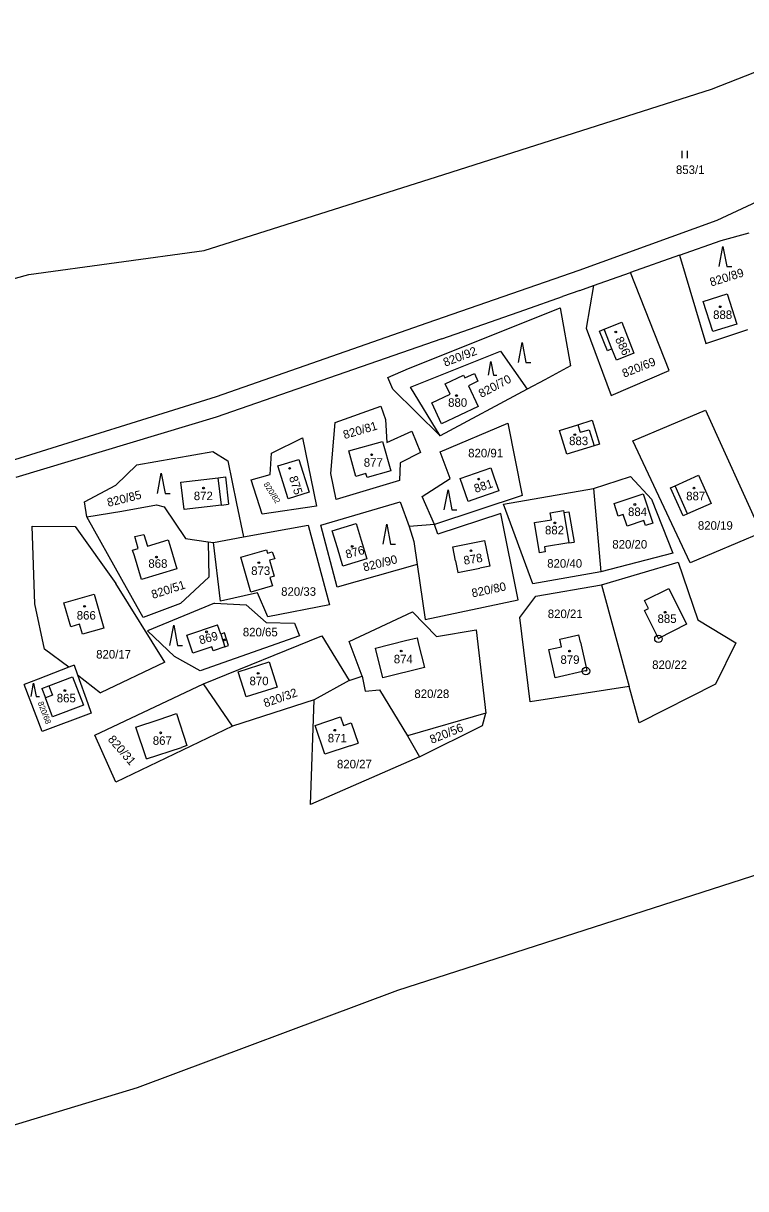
# Model space of a CAD drawing. Extents: x -779596 to -776743, y -1030330 to -1024513.
# Drawn here: x -778278.9 to -778135, y -1026649.8 to -1026417.6 of the extents above; entities that cross this region are included whole.
import ezdxf

# ---------------------------------------------------------------- set-up
doc = ezdxf.new("R2010")
doc.units = 0
for name, color, linetype in [('hranice parcel', 7, 'Continuous'), ('hranice vnitřní', 7, 'Continuous'), ('K_Ú_ hranice', 7, 'Continuous'), ('kultura', 7, 'Continuous'), ('Kód', 7, 'Continuous'), ('č_pacel stav_', 7, 'Continuous'), ('č_parcel poz_', 7, 'Continuous')]:
    doc.layers.add(name, color=color, linetype=linetype)

msp = doc.modelspace()

# ---------------------------------------------------------------- linework, layer by layer
at = {"layer": 'hranice parcel'}
for points in [[(-778140.67, -1026456.85), (-778120.81, -1026447.58)], [(-778168.21, -1026466.82), (-778140.67, -1026456.85)], [(-778139.89, -1026460.93), (-778134.32, -1026459.36)], [(-778148.19, -1026463.85), (-778139.89, -1026460.93)], [(-778148.19, -1026463.85), (-778157.94, -1026467.29)], [(-778148.19, -1026463.85), (-778142.95, -1026481.44)], [(-778198.44, -1026477.3), (-778168.21, -1026466.82)], [(-778165.32, -1026469.89), (-778157.94, -1026467.29)], [(-778150.27, -1026486.79), (-778157.94, -1026467.29)], [(-778168.08, -1026470.86), (-778171.48, -1026472.05)], [(-778168.08, -1026470.86), (-778165.32, -1026469.89)], [(-778165.32, -1026469.89), (-778166.78, -1026478.37)], [(-778143.46, -1026473.02), (-778138.7, -1026471.52)], [(-778138.7, -1026471.52), (-778136.8, -1026477.57)], [(-778179.03, -1026474.69), (-778171.48, -1026472.05)], [(-778141.57, -1026479.06), (-778143.46, -1026473.02)], [(-778195.58, -1026480.48), (-778179.03, -1026474.69)], [(-778178.4, -1026476.9), (-778172.01, -1026474.34)], [(-778172.01, -1026474.34), (-778169.92, -1026485.88)], [(-778240.45, -1026491.98), (-778198.44, -1026477.3)], [(-778202.16, -1026486.42), (-778178.4, -1026476.9)], [(-778166.78, -1026478.37), (-778161.82, -1026491.78)], [(-778163.21, -1026478.56), (-778159.7, -1026477.18)], [(-778159.7, -1026477.18), (-778157.28, -1026483.36)], [(-778136.8, -1026477.57), (-778141.57, -1026479.06)], [(-778195.58, -1026480.48), (-778240.48, -1026496.1)], [(-778164.14, -1026478.93), (-778163.21, -1026478.56)], [(-778162.58, -1026482.88), (-778164.14, -1026478.93)], [(-778142.95, -1026481.44), (-778134.57, -1026478.6)], [(-778201.77, -1026490.12), (-778183.84, -1026482.92)], [(-778183.84, -1026482.92), (-778178.58, -1026490.54)], [(-778161.67, -1026482.48), (-778162.58, -1026482.88)], [(-778160.78, -1026484.74), (-778161.67, -1026482.48)], [(-778157.28, -1026483.36), (-778160.78, -1026484.74)], [(-778206.29, -1026488.21), (-778202.16, -1026486.42)], [(-778194.9, -1026489.43), (-778191.25, -1026487.72)], [(-778191.25, -1026487.72), (-778190.98, -1026488.29)], [(-778190.98, -1026488.29), (-778189.06, -1026487.39)], [(-778189.06, -1026487.39), (-778188.36, -1026488.95)], [(-778169.92, -1026485.88), (-778175.06, -1026488.65)], [(-778161.82, -1026491.78), (-778150.27, -1026486.79)], [(-778205.29, -1026490.51), (-778206.29, -1026488.21)], [(-778195.86, -1026499.83), (-778201.77, -1026490.12)], [(-778193.92, -1026491.51), (-778194.9, -1026489.43)], [(-778188.36, -1026488.95), (-778190.25, -1026489.84)], [(-778190.25, -1026489.84), (-778188.3, -1026494)], [(-778175.06, -1026488.65), (-778178.58, -1026490.54)], [(-778281.69, -1026504.86), (-778240.45, -1026491.98)], [(-778205.29, -1026490.51), (-778195.86, -1026499.83)], [(-778197.56, -1026493.22), (-778193.92, -1026491.51)], [(-778178.58, -1026490.54), (-778195.86, -1026499.83)], [(-778216.78, -1026497.13), (-778207.69, -1026493.91)], [(-778207.69, -1026493.91), (-778206.8, -1026496.54)], [(-778195.59, -1026497.42), (-778197.56, -1026493.22)], [(-778188.3, -1026494), (-778195.59, -1026497.42)], [(-778157.51, -1026500.8), (-778143.02, -1026494.69)], [(-778143.02, -1026494.69), (-778131.92, -1026519.13)], [(-778240.48, -1026496.1), (-778280.39, -1026508.11)], [(-778206.8, -1026496.54), (-778206.52, -1026501.12)], [(-778168.48, -1026497.61), (-778165.61, -1026496.71)], [(-778165.61, -1026496.71), (-778164.16, -1026501.46)], [(-778217.66, -1026507.33), (-778216.78, -1026497.13)], [(-778206.52, -1026501.12), (-778201.52, -1026498.91)], [(-778201.52, -1026498.91), (-778199.83, -1026503.11)], [(-778195.9, -1026503), (-778182.42, -1026497.27)], [(-778182.42, -1026497.27), (-778179.57, -1026511.72)], [(-778172.11, -1026498.74), (-778168.48, -1026497.61)], [(-778170.63, -1026503.48), (-778172.11, -1026498.74)], [(-778229.5, -1026503.25), (-778223.31, -1026500.24)], [(-778223.31, -1026500.24), (-778220.55, -1026513.82)], [(-778214.1, -1026502.83), (-778207.35, -1026500.96)], [(-778207.35, -1026500.96), (-778205.72, -1026506.82)], [(-778164.16, -1026501.46), (-778165.2, -1026501.78)], [(-778146.07, -1026525.15), (-778157.51, -1026500.8)], [(-778256.29, -1026505.58), (-778241.15, -1026502.97)], [(-778241.15, -1026502.97), (-778238.2, -1026504.77)], [(-778229.78, -1026507.52), (-778229.5, -1026503.25)], [(-778212.7, -1026507.89), (-778214.1, -1026502.83)], [(-778199.83, -1026503.11), (-778203.82, -1026505.19)], [(-778193.87, -1026508.32), (-778195.9, -1026503)], [(-778165.2, -1026501.78), (-778170.63, -1026503.48)], [(-778260.5, -1026509.62), (-778256.29, -1026505.58)], [(-778238.2, -1026504.77), (-778236.43, -1026513.27)], [(-778228.21, -1026505.82), (-778224.05, -1026504.52)], [(-778226.15, -1026512.36), (-778228.21, -1026505.82)], [(-778224.05, -1026504.52), (-778222, -1026511.05)], [(-778203.82, -1026505.19), (-778204, -1026508.72)], [(-778191.89, -1026508.3), (-778185.79, -1026506.2)], [(-778185.79, -1026506.2), (-778185.1, -1026508.2)], [(-778247.51, -1026509.03), (-778240.1, -1026508.17)], [(-778240.1, -1026508.17), (-778238.66, -1026508)], [(-778238.66, -1026508), (-778238.02, -1026513.46)], [(-778233.54, -1026508.56), (-778229.78, -1026507.52)], [(-778231.37, -1026515.42), (-778233.54, -1026508.56)], [(-778216.62, -1026512.53), (-778217.66, -1026507.33)], [(-778204, -1026508.72), (-778216.62, -1026512.53)], [(-778210.66, -1026507.32), (-778212.7, -1026507.89)], [(-778210.44, -1026508.12), (-778210.66, -1026507.32)], [(-778205.72, -1026506.82), (-778210.44, -1026508.12)], [(-778199.47, -1026511.89), (-778193.87, -1026508.32)], [(-778190.3, -1026512.9), (-778191.89, -1026508.3)], [(-778185.1, -1026508.2), (-778184.2, -1026510.8)], [(-778165.31, -1026510.3), (-778157.98, -1026507.9)], [(-778157.98, -1026507.9), (-778153.78, -1026512.43)], [(-778149.09, -1026509.76), (-778144.4, -1026507.67)], [(-778144.4, -1026507.67), (-778141.9, -1026513.28)], [(-778266.71, -1026512.96), (-778260.5, -1026509.62)], [(-778246.87, -1026514.5), (-778247.51, -1026509.03)], [(-778184.2, -1026510.8), (-778188.22, -1026512.19)], [(-778183.28, -1026513.41), (-778165.31, -1026510.3)], [(-778165.31, -1026510.3), (-778163.89, -1026526.93)], [(-778149.97, -1026510.15), (-778149.09, -1026509.76)], [(-778147.46, -1026515.77), (-778149.97, -1026510.15)], [(-778266.28, -1026515.95), (-778266.71, -1026512.96)], [(-778236.43, -1026513.27), (-778235.04, -1026519.97)], [(-778222, -1026511.05), (-778226.15, -1026512.36)], [(-778219.63, -1026517.6), (-778203.86, -1026512.95)], [(-778203.86, -1026512.95), (-778202.03, -1026517.87)], [(-778197, -1026517.48), (-778199.47, -1026511.89)], [(-778179.57, -1026511.72), (-778197, -1026517.48)], [(-778188.22, -1026512.19), (-778190.3, -1026512.9)], [(-778161.25, -1026513.33), (-778155.47, -1026511.37)], [(-778160.39, -1026515.85), (-778161.25, -1026513.33)], [(-778155.47, -1026511.37), (-778153.5, -1026517.2)], [(-778153.78, -1026512.43), (-778149.56, -1026523.17)], [(-778141.9, -1026513.28), (-778146.6, -1026515.38)], [(-778266.28, -1026515.95), (-778259.28, -1026514.85)], [(-778259.28, -1026514.85), (-778252.39, -1026513.58)], [(-778252.39, -1026513.58), (-778250.89, -1026513.99)], [(-778250.89, -1026513.99), (-778246.59, -1026520.27)], [(-778239.42, -1026513.62), (-778246.87, -1026514.5)], [(-778239.42, -1026513.62), (-778238.02, -1026513.46)], [(-778220.55, -1026513.82), (-778231.37, -1026515.42)], [(-778183.77, -1026515.3), (-778196.32, -1026519.38)], [(-778180.34, -1026532.5), (-778183.77, -1026515.3)], [(-778177.43, -1026529.32), (-778183.28, -1026513.41)], [(-778173.95, -1026515.16), (-778171.29, -1026514.72)], [(-778173.72, -1026516.52), (-778173.95, -1026515.16)], [(-778171.29, -1026514.72), (-778171.22, -1026515.12)], [(-778171.22, -1026515.12), (-778170.23, -1026514.95)], [(-778170.23, -1026514.95), (-778169.19, -1026520.97)], [(-778159.42, -1026515.52), (-778160.39, -1026515.85)], [(-778158.64, -1026517.84), (-778159.42, -1026515.52)], [(-778146.6, -1026515.38), (-778147.46, -1026515.77)], [(-778276.65, -1026533.32), (-778277.13, -1026517.79)], [(-778277.13, -1026517.79), (-778268.59, -1026517.9)], [(-778268.59, -1026517.9), (-778260.5, -1026529.26)], [(-778259.31, -1026528.41), (-778266.28, -1026515.95)], [(-778235.04, -1026519.97), (-778222.17, -1026517.63)], [(-778222.17, -1026517.63), (-778217.9, -1026533.51)], [(-778216.39, -1026529.98), (-778219.63, -1026517.6)], [(-778217.4, -1026518.77), (-778212.63, -1026517.3)], [(-778212.63, -1026517.3), (-778211.61, -1026520.63)], [(-778197, -1026517.48), (-778202.03, -1026517.87)], [(-778202.03, -1026517.87), (-778201.1, -1026520.9)], [(-778196.32, -1026519.38), (-778197, -1026517.48)], [(-778177.07, -1026517.07), (-778173.72, -1026516.52)], [(-778176.07, -1026523.12), (-778177.07, -1026517.07)], [(-778155.31, -1026516.71), (-778158.64, -1026517.84)], [(-778154.98, -1026517.69), (-778155.31, -1026516.71)], [(-778153.5, -1026517.2), (-778154.98, -1026517.69)], [(-778256.73, -1026519.88), (-778254.88, -1026519.45)], [(-778256.01, -1026522.26), (-778256.73, -1026519.88)], [(-778254.88, -1026519.45), (-778254.18, -1026521.79)], [(-778246.59, -1026520.27), (-778242.1, -1026520.92)], [(-778241.03, -1026521.06), (-778235.04, -1026519.97)], [(-778216.36, -1026522.15), (-778217.4, -1026518.77)], [(-778131.92, -1026519.13), (-778146.07, -1026525.15)], [(-778257.14, -1026522.6), (-778256.01, -1026522.26)], [(-778256.8, -1026523.72), (-778257.14, -1026522.6)], [(-778254.18, -1026521.79), (-778250.08, -1026520.55)], [(-778250.08, -1026520.55), (-778249.76, -1026521.6)], [(-778249.76, -1026521.6), (-778248.33, -1026526.33)], [(-778242.1, -1026520.92), (-778241.95, -1026527.99)], [(-778242.1, -1026520.92), (-778241.03, -1026521.06)], [(-778239.67, -1026532.74), (-778241.03, -1026521.06)], [(-778235.61, -1026523.97), (-778230.49, -1026522.5)], [(-778230.49, -1026522.5), (-778230.29, -1026523.22)], [(-778215.24, -1026525.79), (-778216.36, -1026522.15)], [(-778211.61, -1026520.63), (-778210.47, -1026524.33)], [(-778201.1, -1026520.9), (-778200.44, -1026525.48)], [(-778193.38, -1026521.93), (-778187.04, -1026520.66)], [(-778192.82, -1026524.71), (-778193.38, -1026521.93)], [(-778187.04, -1026520.66), (-778186.01, -1026525.78)], [(-778170.23, -1026521.14), (-778175.11, -1026521.95)], [(-778175.11, -1026521.95), (-778174.95, -1026522.94)], [(-778170.23, -1026521.14), (-778169.19, -1026520.97)], [(-778255.37, -1026528.46), (-778256.8, -1026523.72)], [(-778233.6, -1026530.94), (-778235.61, -1026523.97)], [(-778230.29, -1026523.22), (-778229.32, -1026522.94)], [(-778228.84, -1026524.31), (-778229.89, -1026524.61)], [(-778229.89, -1026524.61), (-778228.97, -1026527.8)], [(-778229.32, -1026522.94), (-778228.84, -1026524.31)], [(-778210.47, -1026524.33), (-778215.24, -1026525.79)], [(-778192.82, -1026524.71), (-778192.35, -1026527.05)], [(-778174.95, -1026522.94), (-778176.07, -1026523.12)], [(-778149.56, -1026523.17), (-778163.89, -1026526.93)], [(-778248.33, -1026526.33), (-778255.37, -1026528.46)], [(-778200.44, -1026525.48), (-778216.39, -1026529.98)], [(-778200.44, -1026525.48), (-778198.88, -1026536.38)], [(-778192.35, -1026527.05), (-778187.95, -1026526.17)], [(-778186.01, -1026525.78), (-778187.95, -1026526.17)], [(-778163.89, -1026526.93), (-778177.43, -1026529.32)], [(-778163.76, -1026529.48), (-778148.47, -1026525.01)], [(-778148.47, -1026525.01), (-778144.58, -1026536.46)], [(-778250.7, -1026544.92), (-778260.5, -1026529.26)], [(-778255.05, -1026536.01), (-778259.31, -1026528.41)], [(-778241.95, -1026527.99), (-778247.59, -1026533.25)], [(-778228.97, -1026527.8), (-778229.79, -1026528.04)], [(-778229.79, -1026528.04), (-778229.31, -1026529.7)], [(-778176.82, -1026531.74), (-778163.76, -1026529.48)], [(-778163.76, -1026529.48), (-778158.24, -1026549.77)], [(-778270.83, -1026533.06), (-778264.8, -1026531.37)], [(-778264.8, -1026531.37), (-778262.9, -1026538.13)], [(-778232.29, -1026531.12), (-778239.67, -1026532.74)], [(-778229.31, -1026529.7), (-778233.6, -1026530.94)], [(-778230.19, -1026535.88), (-778232.29, -1026531.12)], [(-778179.98, -1026536.04), (-778176.82, -1026531.74)], [(-778155.17, -1026532.64), (-778150.34, -1026530.23)], [(-778150.34, -1026530.23), (-778146.78, -1026537.36)], [(-778274.7, -1026542.33), (-778276.65, -1026533.32)], [(-778269.48, -1026537.86), (-778270.83, -1026533.06)], [(-778247.59, -1026533.25), (-778255.05, -1026536.01)], [(-778240.82, -1026533.18), (-778254.2, -1026538.67)], [(-778240.82, -1026533.18), (-778234.54, -1026533.48)], [(-778234.54, -1026533.48), (-778230.54, -1026537.04)], [(-778217.9, -1026533.51), (-778230.19, -1026535.88)], [(-778198.88, -1026536.38), (-778180.34, -1026532.5)], [(-778155.18, -1026534.64), (-778154.37, -1026534.24)], [(-778154.37, -1026534.24), (-778155.17, -1026532.64)], [(-778214, -1026540.8), (-778201.4, -1026534.9)], [(-778201.4, -1026534.9), (-778196.6, -1026539.8)], [(-778177.94, -1026552.82), (-778179.98, -1026536.04)], [(-778152.42, -1026540.17), (-778155.18, -1026534.64)], [(-778144.58, -1026536.46), (-778137, -1026541.09)], [(-778267.7, -1026537.36), (-778269.48, -1026537.86)], [(-778267.15, -1026539.32), (-778267.7, -1026537.36)], [(-778262.9, -1026538.13), (-778267.15, -1026539.32)], [(-778248.78, -1026543.81), (-778254.2, -1026538.67)], [(-778246.35, -1026539.51), (-778240.21, -1026537.46)], [(-778239.6, -1026539.31), (-778240.21, -1026537.46)], [(-778230.54, -1026537.04), (-778224.93, -1026537.16)], [(-778224.93, -1026537.16), (-778223.91, -1026539.66)], [(-778196.6, -1026539.8), (-778188.7, -1026538.5)], [(-778188.7, -1026538.5), (-778186.8, -1026555.1)], [(-778146.78, -1026537.36), (-778152.42, -1026540.17)], [(-778245.15, -1026543.11), (-778246.35, -1026539.51)], [(-778223.91, -1026539.66), (-778243.68, -1026546.61)], [(-778243.06, -1026549.26), (-778219.48, -1026539.65)], [(-778238.87, -1026539.08), (-778239.6, -1026539.31)], [(-778238.04, -1026541.61), (-778238.87, -1026539.08)], [(-778219.48, -1026539.65), (-778214.02, -1026548.54)], [(-778211.4, -1026547.7), (-778214, -1026540.8)], [(-778208.76, -1026542.1), (-778202.78, -1026540.61)], [(-778202.78, -1026540.61), (-778200.49, -1026540.04)], [(-778200.49, -1026540.04), (-778200.18, -1026541.3)], [(-778172.06, -1026540.36), (-778168.25, -1026539.49)], [(-778171.73, -1026541.83), (-778172.06, -1026540.36)], [(-778167.92, -1026540.95), (-778168.25, -1026539.49)], [(-778167.92, -1026540.95), (-778166.64, -1026546.59)], [(-778137, -1026541.09), (-778141.05, -1026549.29)], [(-778269.83, -1026545.94), (-778274.7, -1026542.33)], [(-778241.38, -1026541.85), (-778245.15, -1026543.11)], [(-778241.11, -1026542.64), (-778241.38, -1026541.85)], [(-778238.75, -1026541.85), (-778241.11, -1026542.64)], [(-778238.75, -1026541.85), (-778238.04, -1026541.61)], [(-778207.28, -1026548.06), (-778208.76, -1026542.1)], [(-778200.18, -1026541.3), (-778199.01, -1026546)], [(-778174.22, -1026542.4), (-778171.73, -1026541.83)], [(-778172.94, -1026548.02), (-778174.22, -1026542.4)], [(-778268.78, -1026545.54), (-778269.83, -1026545.94)], [(-778268.78, -1026545.54), (-778268.11, -1026547.43)], [(-778250.7, -1026544.92), (-778263.56, -1026551.03)], [(-778243.68, -1026546.61), (-778248.78, -1026543.81)], [(-778236.13, -1026546.83), (-778229.97, -1026544.85)], [(-778229.97, -1026544.85), (-778228.36, -1026549.87)], [(-778269.83, -1026545.94), (-778275.96, -1026548.28)], [(-778273.85, -1026549.62), (-778269.12, -1026547.81)], [(-778269.12, -1026547.81), (-778266.96, -1026553.46)], [(-778268.11, -1026547.43), (-778263.56, -1026551.03)], [(-778268.11, -1026547.43), (-778266.08, -1026553.13)], [(-778234.53, -1026551.84), (-778236.13, -1026546.83)], [(-778214.02, -1026548.54), (-778211.4, -1026547.7)], [(-778211.4, -1026547.7), (-778210.8, -1026550.7)], [(-778199.01, -1026546), (-778207.28, -1026548.06)], [(-778166.64, -1026546.59), (-778172.94, -1026548.02)], [(-778275.96, -1026548.28), (-778278.77, -1026549.35)], [(-778275.18, -1026558.72), (-778278.77, -1026549.35)], [(-778275.25, -1026550.15), (-778273.85, -1026549.62)], [(-778275.25, -1026550.15), (-778274.53, -1026552.05)], [(-778264.66, -1026559.49), (-778243.06, -1026549.26)], [(-778237.24, -1026557.67), (-778243.06, -1026549.26)], [(-778228.36, -1026549.87), (-778234.53, -1026551.84)], [(-778214.02, -1026548.54), (-778221, -1026552.4)], [(-778210.8, -1026550.7), (-778208, -1026550.4)], [(-778208, -1026550.4), (-778202.4, -1026559.56)], [(-778158.24, -1026549.77), (-778177.94, -1026552.82)], [(-778156.25, -1026557), (-778158.24, -1026549.77)], [(-778141.05, -1026549.29), (-778156.25, -1026557)], [(-778273.09, -1026555.8), (-778274.53, -1026552.05)], [(-778221, -1026552.4), (-778237.24, -1026557.67)], [(-778221.7, -1026573.3), (-778221, -1026552.4)], [(-778265.4, -1026555.05), (-778275.18, -1026558.72)], [(-778266.96, -1026553.46), (-778273.09, -1026555.8)], [(-778266.08, -1026553.13), (-778265.4, -1026555.05)], [(-778251.85, -1026556.31), (-778248.39, -1026555.16)], [(-778248.39, -1026555.16), (-778246.33, -1026561.54)], [(-778186.8, -1026555.1), (-778202.4, -1026559.56)], [(-778187.47, -1026557.53), (-778186.8, -1026555.1)], [(-778256.48, -1026557.84), (-778251.85, -1026556.31)], [(-778220.78, -1026557.54), (-778215.76, -1026555.82)], [(-778215.76, -1026555.82), (-778215.17, -1026557.55)], [(-778215.17, -1026557.55), (-778213.61, -1026557.02)], [(-778213.61, -1026557.02), (-778212.24, -1026561.02)], [(-778260.49, -1026568.84), (-778264.66, -1026559.49)], [(-778237.24, -1026557.67), (-778260.49, -1026568.84)], [(-778254.37, -1026564.2), (-778256.48, -1026557.84)], [(-778218.83, -1026563.27), (-778220.78, -1026557.54)], [(-778202.4, -1026559.56), (-778200, -1026563.8)], [(-778200, -1026563.8), (-778187.47, -1026557.53)], [(-778254.37, -1026564.2), (-778247.44, -1026561.91)], [(-778246.33, -1026561.54), (-778247.44, -1026561.91)], [(-778213.8, -1026561.55), (-778218.83, -1026563.27)], [(-778213.8, -1026561.55), (-778212.24, -1026561.02)], [(-778200, -1026563.8), (-778221.7, -1026573.3)], [(-778102.55, -1026577.5), (-778204.4, -1026610.34)], [(-778204.4, -1026610.34), (-778256.21, -1026629.71)], [(-778256.21, -1026629.71), (-778322.65, -1026649.82)]]:
    msp.add_lwpolyline(points, dxfattribs=at)
at = {"layer": 'hranice vnitřní'}
for points in [[(-778161.67, -1026482.48), (-778163.21, -1026478.56)], [(-778168.48, -1026497.61), (-778168.01, -1026499.11)], [(-778168.01, -1026499.11), (-778166.19, -1026498.59)], [(-778166.19, -1026498.59), (-778165.2, -1026501.78)], [(-778239.42, -1026513.62), (-778240.1, -1026508.17)], [(-778146.6, -1026515.38), (-778149.09, -1026509.76)], [(-778171.22, -1026515.12), (-778170.23, -1026521.14)], [(-778239.6, -1026539.31), (-778238.75, -1026541.85)], [(-778273.85, -1026549.62), (-778273.13, -1026551.51)], [(-778273.13, -1026551.51), (-778274.53, -1026552.05)]]:
    msp.add_lwpolyline(points, dxfattribs=at)
at = {"layer": 'K_Ú_ hranice'}
for points in [[(-778141.81, -1026430.74), (-778100.86, -1026414.67)], [(-778196.63, -1026448.24), (-778141.81, -1026430.74)], [(-778242.87, -1026462.89), (-778196.63, -1026448.24)], [(-778277.8, -1026467.67), (-778242.87, -1026462.89)], [(-778313.67, -1026477.52), (-778277.8, -1026467.67)]]:
    msp.add_lwpolyline(points, dxfattribs=at)
at = {"layer": 'kultura'}
for points in [[(-778147.647, -1026444.525), (-778147.647, -1026443.025)], [(-778146.613, -1026444.525), (-778146.613, -1026443.025)], [(-778140.29, -1026466.11), (-778139.54, -1026462.11), (-778138.79, -1026466.11), (-778137.79, -1026466.11)], [(-778180.31, -1026485.22), (-778179.56, -1026481.22), (-778178.81, -1026485.22), (-778177.81, -1026485.22)], [(-778186.262, -1026487.71), (-778185.76, -1026485.029), (-778185.257, -1026487.71), (-778184.587, -1026487.71)], [(-778252.18, -1026511.28), (-778251.43, -1026507.28), (-778250.68, -1026511.28), (-778249.68, -1026511.28)], [(-778195.07, -1026514.58), (-778194.32, -1026510.58), (-778193.57, -1026514.58), (-778192.57, -1026514.58)], [(-778207.25, -1026521.4), (-778206.5, -1026517.4), (-778205.75, -1026521.4), (-778204.75, -1026521.4)], [(-778249.71, -1026541.56), (-778248.96, -1026537.56), (-778248.21, -1026541.56), (-778247.21, -1026541.56)], [(-778277.382, -1026551.78), (-778276.88, -1026549.099), (-778276.377, -1026551.78), (-778275.707, -1026551.78)]]:
    msp.add_lwpolyline(points, dxfattribs=at)
for centre in [(-778140.09, -1026474.09), (-778160.9, -1026479.12), (-778192.62, -1026491.79), (-778169.05, -1026499.58), (-778209.53, -1026503.59), (-778225.87, -1026506.3), (-778188.21, -1026508.43), (-778243.01, -1026510.23), (-778145.32, -1026510.22), (-778157.11, -1026513.49), (-778173.03, -1026517.17), (-778213.4, -1026521.85), (-778189.74, -1026522.72), (-778252.4, -1026523.97), (-778232.01, -1026525.08), (-778266.72, -1026533.78), (-778151.06, -1026534.96), (-778242.42, -1026538.87), (-778238.82, -1026540.48), (-778203.63, -1026542.69), (-778170.1, -1026542.7), (-778232.14, -1026547.14), (-778270.64, -1026550.58), (-778251.56, -1026558.99), (-778216.88, -1026558.48)]:
    msp.add_circle(centre, 0.175, dxfattribs=at)
at = {"layer": 'Kód'}
for centre, radius in [((-778152.4, -1026540.26), 0.75), ((-778152.4, -1026540.26), 0.032), ((-778166.85, -1026546.69), 0.75), ((-778166.85, -1026546.69), 0.032)]:
    msp.add_circle(centre, radius, dxfattribs=at)

# ---------------------------------------------------------------- texts
at = {"layer": 'č_pacel stav_'}
for s, p in [('888', (-778141.51, -1026476.53)), ('880', (-778194.3, -1026494.03)), ('883', (-778170.2, -1026501.67)), ('877', (-778211.1, -1026505.98)), ('872', (-778244.96, -1026512.63)), ('887', (-778146.87, -1026512.66)), ('884', (-778158.46, -1026515.8)), ('882', (-778175, -1026519.45)), ('868', (-778254.01, -1026526.11)), ('873', (-778233.53, -1026527.54)), ('885', (-778152.58, -1026537.1)), ('874', (-778205.12, -1026545.15)), ('879', (-778171.92, -1026545.25)), ('870', (-778233.86, -1026549.51)), ('865', (-778272.26, -1026552.92)), ('867', (-778253.13, -1026561.38)), ('871', (-778218.27, -1026560.9))]:
    msp.add_text(s, height=1.7, dxfattribs=at).set_placement(p)
for s, rotation, p in [('886', 295.80235, (-778161.083, -1026480.573)), ('875', 287.80229, (-778226.009, -1026508.099)), ('881', 18.10014, (-778188.823, -1026511.198)), ('876', 15.20012, (-778214.47, -1026524.305)), ('878', 9.40008, (-778191.076, -1026525.511)), ('869', 15.00012, (-778243.659, -1026541.386))]:
    msp.add_text(s, height=1.7, rotation=rotation, dxfattribs=at).set_placement(p)
at = {"layer": 'č_parcel poz_'}
for s, p in [('853/1', (-778148.91, -1026447.65)), ('820/91', (-778190.3, -1026504.1)), ('820/19', (-778144.54, -1026518.53)), ('820/20', (-778161.59, -1026522.28)), ('820/40', (-778174.56, -1026526.09)), ('820/33', (-778227.56, -1026531.69)), ('866', (-778268.279, -1026536.43)), ('820/21', (-778174.45, -1026536.13)), ('820/65', (-778235.189, -1026539.77)), ('820/17', (-778264.41, -1026544.19)), ('820/22', (-778153.65, -1026546.28)), ('820/28', (-778201.02, -1026552.06)), ('820/27', (-778216.44, -1026566.07))]:
    msp.add_text(s, height=1.7, dxfattribs=at).set_placement(p)
for s, height, rotation, p in [('820/89', 1.7, 17.40014, (-778141.869, -1026470.08)), ('820/92', 1.7, 21.00017, (-778194.885, -1026486.062)), ('820/69', 1.7, 21.80017, (-778159.229, -1026488.251)), ('820/70', 1.7, 27.90022, (-778187.677, -1026492.28)), ('820/81', 1.7, 16.40013, (-778214.925, -1026500.482)), ('820/85', 1.7, 14.00011, (-778261.995, -1026513.978)), ('820/82', 1.14, 302.50241, (-778231.104, -1026509.481)), ('820/90', 1.7, 14.20011, (-778211.016, -1026526.858)), ('820/51', 1.7, 17.90014, (-778253.102, -1026532.319)), ('820/80', 1.7, 11.80009, (-778189.436, -1026532.014)), ('820/32', 1.7, 19.40016, (-778230.728, -1026553.955)), ('820/68', 1.14, 290.80231, (-778276.063, -1026553.005)), ('820/56', 1.7, 22.10018, (-778197.55, -1026561.2)), ('820/31', 1.7, 311.00247, (-778262.198, -1026560.379))]:
    msp.add_text(s, height=height, rotation=rotation, dxfattribs=at).set_placement(p)

doc.saveas('drawing.dxf')
